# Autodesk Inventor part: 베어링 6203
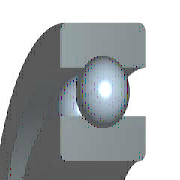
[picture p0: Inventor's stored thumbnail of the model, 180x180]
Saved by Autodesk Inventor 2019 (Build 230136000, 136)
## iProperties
IsCustomPart: 0
Created: 2016-05
Part Number: 베어링 6203
Material: 강, 연강
Description: 깊은 그루브 볼 베어링
Document SubType Name: Modeling
Standard: KS B 2023
Designer: mduedu
Standards Organization: KS
Language: ko-KR
Size Designation: 6203 - 17 x 40 x 12
Categories: <MemberInstance><Categories><Category DisplayName="샤프트 부품" InternalName="7f7aeb1f-a693-4053-b835-cee3144e0d98" Mnemonic="SHFT"><Category DisplayName="베어링" Inter
Density: 1 g/cm^3
Appearance: 노란색
Author: mduedu
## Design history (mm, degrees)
sketch "스케치" dims "d0" = 5.98 (= -0.26 x WD + 0.26 x BD)
  geometry: L1 (3.01, 14.25)-(8.99, 14.25); L2 (6, 14.25)-(6, 11.26); L3 (6, 14.25)-(6, 17.24); L4 (3.778, 12.249)-(0, 12.249); L5 (0, 8.5)-(12, 8.5); L6 (3.778, 16.251)-(0, 16.251); L7 (0, 20)-(12, 20); L8 (12, 8.5)-(12, 12.249); L9 (8.222, 12.249)-(12, 12.249); L10 (8.222, 16.251)-(12, 16.251); L11 (12, 20)-(12, 16.251); L12 (-1.4, 0)-(8.4, 0) reference; L13 (0, -0.3)-(0, 5.3) reference
  constraints: 22 end point, 4 point on line, 2 collinear, 2 perpendicular, 2 symmetric about line, 1 midpoint, 1 parallel, 14 other
  dimensions: "d9" = 17 diameter of L5 L12 (= WD); "d11" = 40 diameter of L7 L12 (= BD); "d12" = 12 distance between parallel lines of L8 L13 (= KB); "d13" = 24.498 diameter of L9 L12 (= 0.326 x BD + 0.674 x WD)
revolve "본체" stored, may be unused: angle "d6" = 90 deg
revolve "볼" stored, may be unused: angle "d7" = 90 deg
pattern_circular "IDS_ARRAYBALL[SIMPL:T]" dims angle "d3" = 360 deg
body "Solid1"
fillet "모깎기1" dims "d1" = 0.6 (= KRS)
other parameters: "WD" = 17 [user parameter; used in 5 equation terms], "BD" = 40 [user parameter; used in 5 equation terms], "KB" = 12 [user parameter; used in 1 equation term], "KRS" = 0.6 [user parameter; used in 1 equation term], "d4" = 0, "d5" = 0, "d8" = 0, "d14" = 0, "d15" = 0, "BBA" = 0 [user parameter], "BC0" = 4750000 [user parameter], "BC" = 9560000 [user parameter], "WR" = 8.5 (= 0.5 x WD) [user parameter]
